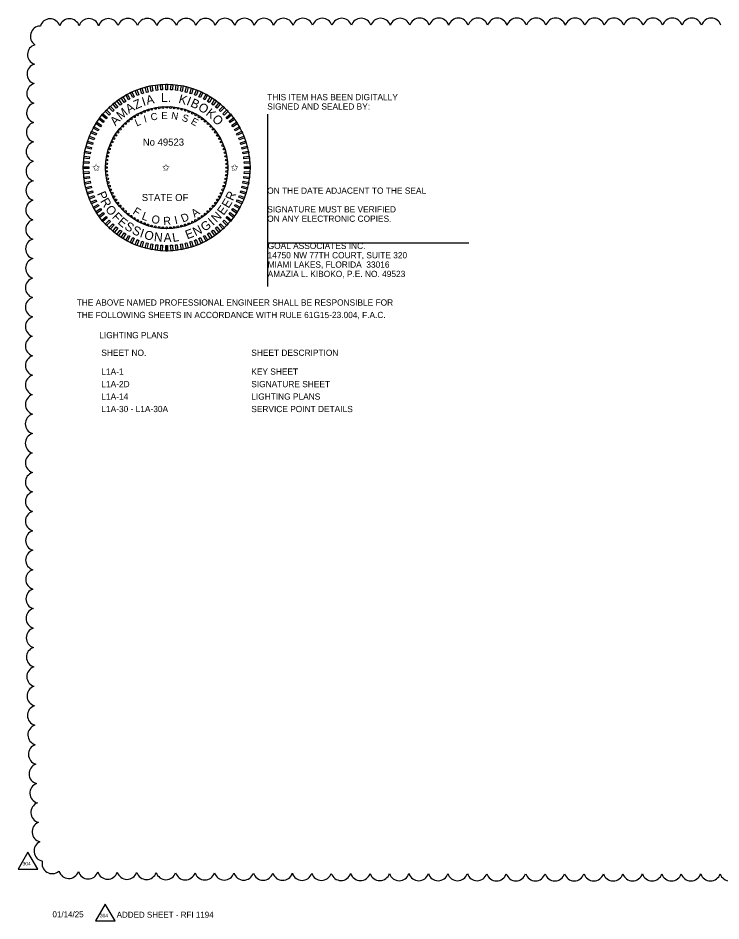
# Model space of a CAD drawing. Extents: x -811.2 to -795.1, y -2226.2 to -2215.9.
# Drawn here: x -811.16 to -803.27, y -2226.01 to -2215.88 of the extents above; entities that cross this region are included whole.
import ezdxf

# ---------------------------------------------------------------- set-up
doc = ezdxf.new("R2010")
doc.units = 0
for name, color, linetype in [('Cloud_dp', 7, 'Continuous'), ('Logo_dp', 7, 'Continuous'), ('NonPlottingEle_dp', 7, 'Continuous'), ('ScratchEle_dp', 7, 'Continuous'), ('TextMinor', 7, 'Continuous'), ('TextMisc', 7, 'Continuous'), ('TextNotes', 7, 'Continuous')]:
    doc.layers.add(name, color=color, linetype=linetype)

msp = doc.modelspace()

# ---------------------------------------------------------------- linework, layer by layer
at = {"layer": 'Cloud_dp'}
for points in [[(-811.049, -2225.244), (-811.157, -2225.432), (-810.937, -2225.432)], [(-810.181, -2225.827), (-810.289, -2226.015), (-810.068, -2226.015)]]:
    msp.add_lwpolyline(points, close=True, dxfattribs=at)
for centre, start, end in [((-810.798, -2216), 18.0566, 163.0566), ((-810.58, -2215.999), 17.7998, 162.7998), ((-810.362, -2215.998), 17.7187, 162.7187), ((-810.143, -2215.997), 17.6743, 162.6743), ((-809.925, -2215.996), 17.6451, 162.6451), ((-809.707, -2215.996), 17.624, 162.624), ((-809.488, -2215.995), 17.6079, 162.6079), ((-809.27, -2215.995), 17.5951, 162.5951), ((-809.052, -2215.995), 17.5845, 162.5845), ((-808.834, -2215.994), 17.5756, 162.5756), ((-808.615, -2215.994), 17.568, 162.568), ((-808.397, -2215.994), 17.5614, 162.5614), ((-808.179, -2215.994), 17.5556, 162.5556), ((-807.96, -2215.993), 17.5505, 162.5505), ((-807.742, -2215.993), 17.5459, 162.5459), ((-807.524, -2215.993), 17.5417, 162.5417), ((-807.305, -2215.993), 17.5379, 162.5379), ((-807.087, -2215.993), 17.5344, 162.5344), ((-806.869, -2215.993), 17.5313, 162.5313), ((-806.65, -2215.992), 17.5283, 162.5283), ((-806.432, -2215.992), 17.5256, 162.5256), ((-806.214, -2215.992), 17.5231, 162.5231), ((-805.995, -2215.992), 17.5207, 162.5207), ((-805.777, -2215.992), 17.5185, 162.5185), ((-805.559, -2215.992), 17.5164, 162.5164), ((-805.34, -2215.992), 17.5145, 162.5145), ((-805.122, -2215.992), 17.5126, 162.5126), ((-804.904, -2215.992), 17.5109, 162.5109), ((-804.685, -2215.992), 17.5092, 162.5092), ((-804.467, -2215.992), 17.5077, 162.5077), ((-804.249, -2215.992), 17.5062, 162.5062), ((-804.03, -2215.992), 17.5048, 162.5048), ((-803.812, -2215.992), 17.5034, 162.5034), ((-803.594, -2215.992), 17.5021, 162.5021), ((-803.375, -2215.992), 17.5009, 162.5009), ((-810.905, -2216.081), 91.4771, 236.4771), ((-810.937, -2216.287), 105.908, 250.908), ((-810.942, -2216.505), 106.4168, 251.4168), ((-810.945, -2216.723), 106.6762, 251.6762), ((-810.948, -2216.941), 106.841, 251.841), ((-810.95, -2217.159), 106.9576, 251.9576), ((-810.952, -2217.377), 107.0457, 252.0457), ((-810.954, -2217.596), 107.1154, 252.1154), ((-810.955, -2217.814), 107.1722, 252.1722), ((-810.956, -2218.032), 107.2198, 252.2198), ((-810.957, -2218.251), 107.2603, 252.2603), ((-810.958, -2218.469), 107.2954, 252.2954), ((-810.959, -2218.687), 107.3262, 252.3262), ((-810.96, -2218.906), 107.3535, 252.3535), ((-810.96, -2219.124), 107.3779, 252.3779), ((-810.96, -2219.342), 107.3998, 252.3998), ((-810.961, -2219.56), 107.4198, 252.4198), ((-810.961, -2219.779), 107.438, 252.438), ((-810.961, -2219.997), 107.4547, 252.4547), ((-810.961, -2220.215), 107.4701, 252.4701), ((-810.962, -2220.434), 107.4843, 252.4843), ((-810.962, -2220.652), 107.499, 252.499), ((-810.961, -2220.87), 107.5356, 252.5356), ((-810.961, -2221.089), 107.5822, 252.5822), ((-810.961, -2221.307), 107.6325, 252.6325), ((-810.96, -2221.525), 107.6869, 252.6869), ((-810.959, -2221.743), 107.7461, 252.7461), ((-810.958, -2221.962), 107.8108, 252.8108), ((-810.957, -2222.18), 107.8818, 252.8818), ((-810.955, -2222.398), 107.9604, 252.9604), ((-810.954, -2222.617), 108.0479, 253.0479), ((-810.951, -2222.835), 108.1461, 253.1461), ((-810.949, -2223.053), 108.2576, 253.2576), ((-810.945, -2223.271), 108.3854, 253.3854), ((-810.942, -2223.489), 108.534, 253.534), ((-810.938, -2223.708), 108.7099, 253.7099), ((-810.933, -2223.926), 108.9225, 253.9225), ((-810.927, -2224.144), 109.1867, 254.1867), ((-810.92, -2224.362), 109.5275, 254.5275), ((-810.911, -2224.58), 109.9909, 254.9909), ((-810.9, -2224.797), 110.6749, 255.6749), ((-810.886, -2225.015), 111.8417, 256.8417), ((-810.864, -2225.23), 114.6718, 259.6718), ((-810.774, -2225.37), 166.2299, 311.2299), ((-810.588, -2225.424), 196.1072, 341.1072), ((-810.37, -2225.429), 196.5738, 341.5738), ((-810.152, -2225.432), 196.7877, 341.7877), ((-809.934, -2225.434), 196.9179, 341.9179), ((-809.715, -2225.436), 197.008, 342.008), ((-809.497, -2225.438), 197.075, 342.075), ((-809.279, -2225.44), 197.1274, 342.1274), ((-809.061, -2225.441), 197.1699, 342.1699), ((-808.842, -2225.442), 197.2052, 342.2052), ((-808.624, -2225.443), 197.2352, 342.2352), ((-808.406, -2225.444), 197.261, 342.261), ((-808.187, -2225.445), 197.2836, 342.2836), ((-807.969, -2225.446), 197.3036, 342.3036), ((-807.751, -2225.446), 197.3214, 342.3214), ((-807.532, -2225.447), 197.3374, 342.3374), ((-807.314, -2225.448), 197.3519, 342.3519), ((-807.096, -2225.448), 197.3651, 342.3651), ((-806.878, -2225.449), 197.3773, 342.3773), ((-806.659, -2225.449), 197.3884, 342.3884), ((-806.441, -2225.45), 197.3987, 342.3987), ((-806.223, -2225.45), 197.4083, 342.4083), ((-806.004, -2225.45), 197.4172, 342.4172), ((-805.786, -2225.451), 197.4256, 342.4256), ((-805.568, -2225.451), 197.4334, 342.4334), ((-805.349, -2225.451), 197.4407, 342.4407), ((-805.131, -2225.451), 197.4476, 342.4476), ((-804.913, -2225.451), 197.4542, 342.4542), ((-804.694, -2225.452), 197.4604, 342.4604), ((-804.476, -2225.452), 197.4662, 342.4662), ((-804.258, -2225.452), 197.4718, 342.4718), ((-804.039, -2225.452), 197.4771, 342.4771), ((-803.821, -2225.452), 197.4821, 342.4821), ((-803.603, -2225.452), 197.487, 342.487), ((-803.384, -2225.452), 197.4916, 342.4916), ((-803.166, -2225.452), 197.496, 342.496)]:
    msp.add_arc(centre, 0.114, start, end, dxfattribs=at)
at = {"layer": 'Logo_dp'}
for p, q in [((-809.499, -2218.493), (-809.499, -2218.43)), ((-809.489, -2218.493), (-809.489, -2218.43)), ((-809.479, -2218.493), (-809.479, -2218.43))]:
    msp.add_line(p, q, dxfattribs=at)
for points in [[(-809.852, -2216.762), (-809.87, -2216.77), (-809.897, -2216.714), (-809.878, -2216.705)], [(-809.801, -2216.74), (-809.82, -2216.748), (-809.843, -2216.69), (-809.824, -2216.683)], [(-809.749, -2216.722), (-809.768, -2216.729), (-809.788, -2216.669), (-809.769, -2216.663)], [(-809.696, -2216.708), (-809.716, -2216.713), (-809.731, -2216.652), (-809.712, -2216.647)], [(-809.643, -2216.696), (-809.662, -2216.7), (-809.674, -2216.639), (-809.654, -2216.635)], [(-809.588, -2216.688), (-809.608, -2216.691), (-809.616, -2216.629), (-809.596, -2216.627)], [(-809.534, -2216.684), (-809.554, -2216.685), (-809.558, -2216.623), (-809.538, -2216.622)], [(-809.479, -2216.683), (-809.499, -2216.683), (-809.499, -2216.621), (-809.479, -2216.621)], [(-809.424, -2216.685), (-809.444, -2216.684), (-809.44, -2216.622), (-809.42, -2216.623)], [(-809.369, -2216.691), (-809.389, -2216.688), (-809.382, -2216.627), (-809.362, -2216.629)], [(-809.315, -2216.7), (-809.335, -2216.696), (-809.323, -2216.635), (-809.304, -2216.639)], [(-809.262, -2216.713), (-809.281, -2216.708), (-809.266, -2216.647), (-809.246, -2216.652)], [(-809.209, -2216.729), (-809.228, -2216.723), (-809.209, -2216.663), (-809.19, -2216.669)], [(-809.158, -2216.748), (-809.177, -2216.741), (-809.154, -2216.683), (-809.135, -2216.69)], [(-809.108, -2216.77), (-809.126, -2216.762), (-809.099, -2216.705), (-809.081, -2216.714)], [(-809.994, -2216.844), (-810.011, -2216.856), (-810.047, -2216.805), (-810.031, -2216.793)], [(-809.948, -2216.813), (-809.966, -2216.824), (-809.999, -2216.772), (-809.982, -2216.761)], [(-809.901, -2216.786), (-809.919, -2216.796), (-809.949, -2216.741), (-809.931, -2216.731)], [(-809.059, -2216.796), (-809.077, -2216.786), (-809.047, -2216.731), (-809.029, -2216.741)], [(-809.012, -2216.824), (-809.029, -2216.814), (-808.996, -2216.761), (-808.979, -2216.772)], [(-808.967, -2216.856), (-808.983, -2216.844), (-808.947, -2216.793), (-808.931, -2216.805)], [(-810.119, -2216.951), (-810.133, -2216.966), (-810.178, -2216.923), (-810.164, -2216.908)], [(-810.08, -2216.913), (-810.094, -2216.926), (-810.137, -2216.881), (-810.122, -2216.867)], [(-810.038, -2216.877), (-810.054, -2216.89), (-810.093, -2216.842), (-810.078, -2216.829)], [(-808.924, -2216.89), (-808.94, -2216.877), (-808.9, -2216.829), (-808.884, -2216.842)], [(-808.883, -2216.927), (-808.898, -2216.913), (-808.855, -2216.867), (-808.841, -2216.881)], [(-808.845, -2216.966), (-808.859, -2216.951), (-808.813, -2216.909), (-808.8, -2216.923)], [(-810.19, -2217.035), (-810.202, -2217.051), (-810.252, -2217.014), (-810.24, -2216.998)], [(-810.156, -2216.992), (-810.168, -2217.007), (-810.217, -2216.968), (-810.204, -2216.952)], [(-808.809, -2217.007), (-808.822, -2216.992), (-808.774, -2216.952), (-808.761, -2216.968)], [(-808.776, -2217.051), (-808.788, -2217.035), (-808.738, -2216.998), (-808.726, -2217.015)], [(-810.25, -2217.127), (-810.259, -2217.144), (-810.314, -2217.114), (-810.304, -2217.097)], [(-810.221, -2217.08), (-810.232, -2217.097), (-810.285, -2217.063), (-810.274, -2217.046)], [(-808.746, -2217.097), (-808.757, -2217.08), (-808.704, -2217.047), (-808.693, -2217.064)], [(-808.718, -2217.145), (-808.728, -2217.127), (-808.674, -2217.097), (-808.664, -2217.115)], [(-810.298, -2217.225), (-810.305, -2217.244), (-810.363, -2217.221), (-810.355, -2217.203)], [(-810.275, -2217.175), (-810.284, -2217.194), (-810.34, -2217.167), (-810.332, -2217.149)], [(-808.694, -2217.194), (-808.703, -2217.176), (-808.646, -2217.149), (-808.638, -2217.167)], [(-808.673, -2217.244), (-808.68, -2217.226), (-808.622, -2217.203), (-808.615, -2217.221)], [(-810.333, -2217.329), (-810.338, -2217.349), (-810.398, -2217.333), (-810.393, -2217.314)], [(-810.317, -2217.277), (-810.323, -2217.296), (-810.382, -2217.277), (-810.376, -2217.258)], [(-808.655, -2217.296), (-808.661, -2217.277), (-808.602, -2217.258), (-808.596, -2217.277)], [(-808.64, -2217.349), (-808.645, -2217.33), (-808.585, -2217.314), (-808.58, -2217.334)], [(-810.354, -2217.437), (-810.357, -2217.457), (-810.419, -2217.449), (-810.416, -2217.429)], [(-810.345, -2217.383), (-810.349, -2217.403), (-810.41, -2217.391), (-810.406, -2217.371)], [(-808.629, -2217.403), (-808.633, -2217.383), (-808.571, -2217.371), (-808.568, -2217.391)], [(-808.621, -2217.457), (-808.623, -2217.437), (-808.562, -2217.429), (-808.559, -2217.449)], [(-810.36, -2217.492), (-810.362, -2217.512), (-810.424, -2217.508), (-810.422, -2217.488)], [(-808.616, -2217.512), (-808.618, -2217.492), (-808.555, -2217.488), (-808.554, -2217.508)], [(-810.363, -2217.546), (-810.363, -2217.567), (-810.425, -2217.567), (-810.425, -2217.546)], [(-810.362, -2217.601), (-810.36, -2217.621), (-810.422, -2217.625), (-810.424, -2217.605)], [(-808.618, -2217.622), (-808.616, -2217.601), (-808.554, -2217.605), (-808.555, -2217.625)], [(-808.615, -2217.567), (-808.615, -2217.547), (-808.553, -2217.547), (-808.553, -2217.567)], [(-810.357, -2217.656), (-810.354, -2217.676), (-810.416, -2217.684), (-810.419, -2217.664)], [(-810.349, -2217.71), (-810.345, -2217.73), (-810.407, -2217.742), (-810.41, -2217.722)], [(-808.633, -2217.73), (-808.629, -2217.71), (-808.568, -2217.722), (-808.571, -2217.742)], [(-808.623, -2217.676), (-808.621, -2217.656), (-808.559, -2217.664), (-808.562, -2217.684)], [(-810.338, -2217.764), (-810.333, -2217.783), (-810.393, -2217.799), (-810.398, -2217.779)], [(-810.323, -2217.817), (-810.317, -2217.836), (-810.376, -2217.855), (-810.382, -2217.836)], [(-808.661, -2217.836), (-808.655, -2217.817), (-808.596, -2217.836), (-808.602, -2217.855)], [(-808.645, -2217.784), (-808.64, -2217.764), (-808.58, -2217.78), (-808.585, -2217.799)], [(-810.305, -2217.869), (-810.298, -2217.887), (-810.356, -2217.91), (-810.363, -2217.892)], [(-810.284, -2217.919), (-810.275, -2217.938), (-810.332, -2217.964), (-810.34, -2217.946)], [(-808.703, -2217.938), (-808.694, -2217.92), (-808.638, -2217.946), (-808.646, -2217.964)], [(-808.68, -2217.888), (-808.673, -2217.869), (-808.615, -2217.892), (-808.622, -2217.911)], [(-810.259, -2217.969), (-810.25, -2217.986), (-810.304, -2218.016), (-810.314, -2217.999)], [(-810.232, -2218.016), (-810.221, -2218.033), (-810.274, -2218.067), (-810.285, -2218.05)], [(-808.757, -2218.033), (-808.746, -2218.016), (-808.693, -2218.05), (-808.704, -2218.067)], [(-808.728, -2217.986), (-808.719, -2217.969), (-808.664, -2217.999), (-808.674, -2218.016)], [(-810.202, -2218.062), (-810.19, -2218.078), (-810.24, -2218.115), (-810.252, -2218.098)], [(-810.169, -2218.106), (-810.156, -2218.121), (-810.204, -2218.161), (-810.217, -2218.145)], [(-808.822, -2218.121), (-808.809, -2218.106), (-808.761, -2218.145), (-808.774, -2218.161)], [(-808.788, -2218.078), (-808.776, -2218.062), (-808.726, -2218.099), (-808.738, -2218.115)], [(-810.133, -2218.147), (-810.119, -2218.162), (-810.164, -2218.205), (-810.178, -2218.19)], [(-810.094, -2218.186), (-810.08, -2218.2), (-810.122, -2218.246), (-810.137, -2218.232)], [(-810.054, -2218.223), (-810.038, -2218.236), (-810.078, -2218.284), (-810.093, -2218.271)], [(-808.94, -2218.236), (-808.924, -2218.223), (-808.885, -2218.271), (-808.9, -2218.284)], [(-808.898, -2218.2), (-808.884, -2218.187), (-808.841, -2218.232), (-808.856, -2218.246)], [(-808.859, -2218.162), (-808.845, -2218.147), (-808.8, -2218.19), (-808.814, -2218.205)], [(-810.011, -2218.257), (-809.994, -2218.269), (-810.031, -2218.32), (-810.047, -2218.308)], [(-809.966, -2218.289), (-809.949, -2218.3), (-809.982, -2218.352), (-809.999, -2218.341)], [(-809.919, -2218.317), (-809.901, -2218.327), (-809.931, -2218.382), (-809.949, -2218.372)], [(-809.87, -2218.343), (-809.852, -2218.351), (-809.878, -2218.408), (-809.897, -2218.399)], [(-809.126, -2218.351), (-809.108, -2218.343), (-809.081, -2218.399), (-809.1, -2218.408)], [(-809.077, -2218.327), (-809.059, -2218.317), (-809.029, -2218.372), (-809.047, -2218.382)], [(-809.029, -2218.3), (-809.012, -2218.289), (-808.979, -2218.342), (-808.996, -2218.352)], [(-808.984, -2218.269), (-808.967, -2218.257), (-808.931, -2218.308), (-808.947, -2218.32)], [(-809.82, -2218.365), (-809.801, -2218.373), (-809.824, -2218.431), (-809.843, -2218.423)], [(-809.769, -2218.384), (-809.749, -2218.391), (-809.769, -2218.45), (-809.788, -2218.444)], [(-809.716, -2218.4), (-809.697, -2218.405), (-809.712, -2218.466), (-809.732, -2218.461)], [(-809.663, -2218.413), (-809.643, -2218.417), (-809.655, -2218.478), (-809.674, -2218.474)], [(-809.609, -2218.422), (-809.589, -2218.425), (-809.596, -2218.486), (-809.616, -2218.484)], [(-809.554, -2218.428), (-809.534, -2218.429), (-809.538, -2218.491), (-809.558, -2218.49)], [(-809.499, -2218.43), (-809.479, -2218.43), (-809.479, -2218.493), (-809.499, -2218.493)], [(-809.444, -2218.429), (-809.424, -2218.428), (-809.42, -2218.49), (-809.44, -2218.491)], [(-809.39, -2218.425), (-809.37, -2218.422), (-809.362, -2218.484), (-809.382, -2218.486)], [(-809.335, -2218.417), (-809.315, -2218.413), (-809.304, -2218.474), (-809.324, -2218.478)], [(-809.282, -2218.405), (-809.262, -2218.4), (-809.246, -2218.461), (-809.266, -2218.466)], [(-809.229, -2218.391), (-809.209, -2218.384), (-809.19, -2218.444), (-809.209, -2218.45)], [(-809.177, -2218.373), (-809.158, -2218.365), (-809.135, -2218.423), (-809.154, -2218.431)]]:
    msp.add_lwpolyline(points, close=True, dxfattribs=at)
for centre in [(-809.737, -2216.927), (-809.697, -2216.913), (-809.657, -2216.901), (-809.615, -2216.892), (-809.573, -2216.885), (-809.531, -2216.881), (-809.488, -2216.88), (-809.446, -2216.881), (-809.404, -2216.886), (-809.362, -2216.892), (-809.32, -2216.902), (-809.279, -2216.913), (-809.239, -2216.928), (-809.92, -2217.035), (-809.886, -2217.009), (-809.851, -2216.985), (-809.814, -2216.964), (-809.776, -2216.944), (-809.2, -2216.945), (-809.163, -2216.964), (-809.126, -2216.986), (-809.091, -2217.01), (-810.01, -2217.125), (-809.982, -2217.093), (-809.952, -2217.063), (-809.057, -2217.036), (-809.025, -2217.064), (-808.995, -2217.094), (-808.967, -2217.126), (-810.081, -2217.23), (-810.06, -2217.194), (-810.036, -2217.158), (-808.941, -2217.159), (-808.918, -2217.195), (-808.896, -2217.231), (-810.118, -2217.307), (-810.101, -2217.268), (-808.877, -2217.269), (-808.86, -2217.308), (-810.153, -2217.429), (-810.144, -2217.388), (-810.132, -2217.347), (-808.845, -2217.348), (-808.834, -2217.389), (-808.824, -2217.43), (-810.164, -2217.514), (-810.16, -2217.471), (-808.818, -2217.472), (-808.814, -2217.515), (-810.165, -2217.556), (-810.164, -2217.598), (-810.16, -2217.641), (-808.818, -2217.642), (-808.814, -2217.6), (-808.813, -2217.557), (-810.153, -2217.683), (-810.144, -2217.724), (-808.834, -2217.725), (-808.825, -2217.684), (-810.132, -2217.765), (-810.118, -2217.805), (-810.101, -2217.844), (-808.877, -2217.845), (-808.86, -2217.806), (-808.846, -2217.766), (-810.082, -2217.882), (-810.06, -2217.919), (-808.918, -2217.919), (-808.896, -2217.883), (-810.037, -2217.954), (-810.01, -2217.987), (-809.982, -2218.019), (-808.996, -2218.02), (-808.968, -2217.988), (-808.942, -2217.955), (-809.952, -2218.049), (-809.921, -2218.077), (-809.887, -2218.103), (-809.852, -2218.127), (-809.815, -2218.149), (-809.164, -2218.15), (-809.127, -2218.128), (-809.092, -2218.104), (-809.058, -2218.078), (-809.026, -2218.05), (-809.777, -2218.168), (-809.738, -2218.185), (-809.699, -2218.2), (-809.658, -2218.212), (-809.616, -2218.221), (-809.574, -2218.228), (-809.532, -2218.232), (-809.489, -2218.233), (-809.447, -2218.232), (-809.405, -2218.228), (-809.363, -2218.221), (-809.321, -2218.212), (-809.28, -2218.2), (-809.24, -2218.186), (-809.201, -2218.169)]:
    msp.add_circle(centre, 0.00998, dxfattribs=at)
at = {"layer": 'NonPlottingEle_dp'}
for radius in [0.936, 0.686]:
    msp.add_circle((-809.489, -2217.557), radius, dxfattribs=at)
at = {"layer": 'ScratchEle_dp'}
for p, q in [((-808.355, -2216.955), (-808.355, -2218.89)), ((-808.355, -2218.4), (-806.098, -2218.4))]:
    msp.add_line(p, q, dxfattribs=at)

# ---------------------------------------------------------------- texts
at = {"layer": 'Cloud_dp'}
for p in [(-811.107, -2225.392), (-810.239, -2225.975)]:
    msp.add_text('304', height=0.04, rotation=0, dxfattribs=at).set_placement(p)
at = {"layer": 'Logo_dp'}
for s, rotation, p in [('L', 23.3052, (-809.825, -2217.095)), ('I', 14.8189, (-809.734, -2217.052)), ('C', 8.9826, (-809.662, -2217.029)), ('E', 359.9662, (-809.549, -2217.011)), ('N', 350.6464, (-809.442, -2217.009)), ('S', 341.04, (-809.325, -2217.028)), ('E', 331.1686, (-809.224, -2217.06))]:
    msp.add_text(s, height=0.0799, rotation=rotation, dxfattribs=at).set_placement(p)
for p in [(-810.323, -2217.594), (-809.539, -2217.594), (-808.768, -2217.594)]:
    msp.add_text('✩', height=0.0799, dxfattribs=at).set_placement(p)
at = {"layer": 'TextMinor'}
for s, p in [('01/14/25', (-810.771, -2225.975)), ('ADDED SHEET - RFI 1194', (-810.05, -2225.979))]:
    msp.add_text(s, height=0.0672, dxfattribs=at).set_placement(p)
at = {"layer": 'TextMisc'}
for s, height, rotation, p in [('L', 0.0998, 359.9662, (-809.552, -2216.82)), ('Z', 0.0998, 23.3052, (-809.835, -2216.904)), ('I', 0.0998, 17.6836, (-809.749, -2216.867)), ('A', 0.0998, 11.9184, (-809.709, -2216.851)), ('.', 0.0998, 353.7858, (-809.476, -2216.818)), ('K', 0.0998, 344.2727, (-809.362, -2216.828)), ('I', 0.0998, 337.7777, (-809.274, -2216.849)), ('B', 0.0998, 334.487, (-809.23, -2216.865)), ('M', 0.0998, 39.3, (-810.002, -2217.025)), ('A', 0.0998, 31.466, (-809.913, -2216.953)), ('O', 0.0998, 327.8239, (-809.145, -2216.903)), ('K', 0.0998, 321.0594, (-809.056, -2216.96)), ('A', 0.0998, 46.8094, (-810.064, -2217.093)), ('O', 0.0998, 314.2033, (-808.986, -2217.018)), ('P', 0.0999, 293.1955, (-810.273, -2217.848)), ('R', 0.0999, 65.2886, (-808.744, -2217.937)), ('R', 0.0999, 300.2595, (-810.237, -2217.933)), ('E', 0.0999, 58.6169, (-808.793, -2218.021)), ('O', 0.0999, 307.2662, (-810.183, -2218.025)), ('F', 0.0899, 328.534, (-809.877, -2218.071)), ('A', 0.0899, 35.5463, (-809.175, -2218.12)), ('E', 0.0999, 53.9986, (-808.85, -2218.099)), ('F', 0.0999, 314.2033, (-810.109, -2218.117)), ('E', 0.0999, 321.0594, (-810.046, -2218.181)), ('L', 0.0899, 339.4875, (-809.776, -2218.134)), ('O', 0.0899, 348.0816, (-809.666, -2218.174)), ('R', 0.0899, 3.1074, (-809.525, -2218.201)), ('I', 0.0899, 12.5248, (-809.391, -2218.192)), ('D', 0.0899, 22.2223, (-809.307, -2218.175)), ('I', 0.0999, 41.8391, (-808.969, -2218.213)), ('N', 0.0999, 44.3421, (-808.93, -2218.179)), ('S', 0.0999, 327.8239, (-809.97, -2218.241)), ('S', 0.0999, 334.487, (-809.887, -2218.293)), ('E', 0.0999, 20.5125, (-809.258, -2218.362)), ('N', 0.0999, 26.0618, (-809.166, -2218.329)), ('G', 0.0999, 34.1136, (-809.065, -2218.279)), ('I', 0.0999, 341.04, (-809.798, -2218.334)), ('O', 0.0999, 344.2727, (-809.749, -2218.352)), ('N', 0.0999, 353.7858, (-809.635, -2218.381)), ('A', 0.0999, 359.9662, (-809.523, -2218.392)), ('L', 0.0999, 8.9826, (-809.418, -2218.392))]:
    msp.add_text(s, height=height, rotation=rotation, dxfattribs=at).set_placement(p)
for s, height, p in [('THIS ITEM HAS BEEN DIGITALLY', 0.07, (-808.36, -2216.8)), ('SIGNED AND SEALED BY:', 0.07, (-808.36, -2216.905)), ('No 49523', 0.0799, (-809.757, -2217.31)), ('ON THE DATE ADJACENT TO THE SEAL', 0.07, (-808.36, -2217.85)), ('STATE OF', 0.0799, (-809.768, -2217.932)), ('SIGNATURE MUST BE VERIFIED ', 0.07, (-808.36, -2218.06)), ('ON ANY ELECTRONIC COPIES.', 0.07, (-808.36, -2218.165)), ('GOAL ASSOCIATES INC.', 0.07, (-808.355, -2218.47)), ('14750 NW 77TH COURT, SUITE 320', 0.07, (-808.355, -2218.575)), ('MIAMI LAKES, FLORIDA  33016', 0.07, (-808.355, -2218.68)), ('AMAZIA L. KIBOKO, P.E. NO. 49523', 0.07, (-808.355, -2218.785)), ('THE ABOVE NAMED PROFESSIONAL ENGINEER SHALL BE RESPONSIBLE FOR ', 0.07, (-810.499, -2219.106)), ('THE FOLLOWING SHEETS IN ACCORDANCE WITH RULE 61G15-23.004, F.A.C.', 0.07, (-810.499, -2219.246)), ('LIGHTING PLANS', 0.07, (-810.245, -2219.473))]:
    msp.add_text(s, height=height, dxfattribs=at).set_placement(p)
at = {"layer": 'TextNotes'}
for s, p in [('SHEET NO.', (-810.222, -2219.67)), ('SHEET DESCRIPTION', (-808.539, -2219.67)), ('L1A-1', (-810.222, -2219.882)), ('KEY SHEET', (-808.539, -2219.882)), ('L1A-2D', (-810.222, -2220.022)), ('SIGNATURE SHEET', (-808.539, -2220.022)), ('L1A-14', (-810.222, -2220.162)), ('LIGHTING PLANS', (-808.539, -2220.162)), ('L1A-30 - L1A-30A', (-810.222, -2220.302)), ('SERVICE POINT DETAILS', (-808.539, -2220.302))]:
    msp.add_text(s, height=0.07, dxfattribs=at).set_placement(p)

doc.saveas('drawing.dxf')
